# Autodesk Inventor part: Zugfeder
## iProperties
Created: 2008-08
Part Number: Zugfeder
Document SubType Name: Modeling
Designer: U.Rapp
Material: Federstahl
Author: U.Rapp
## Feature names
1. Spirale1
2. Sweeping
3. Trennen1
